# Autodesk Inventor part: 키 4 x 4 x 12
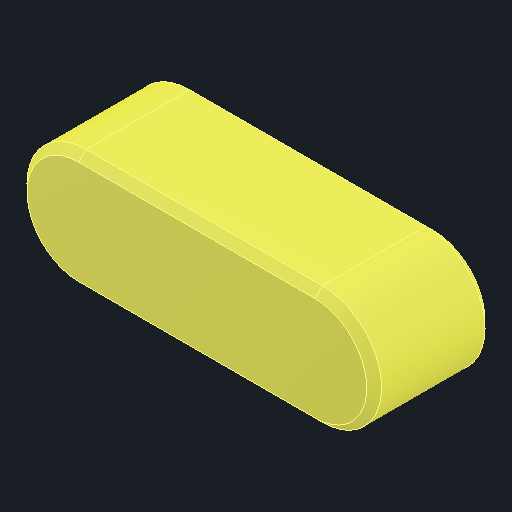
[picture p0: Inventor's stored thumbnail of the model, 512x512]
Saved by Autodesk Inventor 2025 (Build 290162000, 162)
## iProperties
Created: 2025-08
Part Number: 키 4 x 4 x 12
Material: 강철, 연강
Description: 키 및 해당 키홈
Document SubType Name: Modeling
Designer: infra006
Density: 7.85 g/cm^3
Appearance: 기본값
Author: jhkim
Sending System: Autodesk Inventor 2026
Preprocessor: ST-DEVELOPER v20.1
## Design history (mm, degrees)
feature "Solid1"
node "솔리드1"
